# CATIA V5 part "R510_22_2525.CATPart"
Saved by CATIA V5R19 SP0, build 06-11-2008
Material "Steel": density 7860 kg/m3, Young's modulus 2e+11 Pa, Poisson ratio 0.266, thermal expansion 1.17e-05 1/K
Bounding box of the stored display mesh (mm): x -12.497 to 12.497, y -12.358 to 12.439, z 0 to 96
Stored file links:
  G:\Podręcznik\CD\Narzędzia\Arkusz Excel\Modele narzędzi\R510.22-2525.CATPart
  C:\Program Files\Dassault Systemes\B19\intel_a\startup\materials\Catalog.CATMaterial
  F:\OSTATNIE\DesignTable2.xls
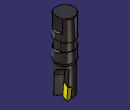
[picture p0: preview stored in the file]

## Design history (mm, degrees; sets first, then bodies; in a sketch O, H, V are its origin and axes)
Parameters
  CuttingType = "CUTTER"
  d = 25 mm {design table}
  D = 25 mm {design table}
  L = 96 mm {design table}
  l = 56 mm {design table}
  alfa = 11 deg {design table}
  gammap = 4 deg {design table}
  S = 4.76 mm {design table}
  epsilon = 85 deg {design table}
  lp = 16 mm {design table}
  x = 0.591 mm {design table}
  gammaf = -10 deg {design table}
  z = 2 {design table}
  teta = 180 deg {design table}
  `lp'` = 15.961 mm {design table}
  `lp''` = 9.4182 mm {design table}
Body1 "BODY" (main body), material "Steel"
  Sketch1 "sketch" on yz-plane, origin (0, 0, 0), H (0, 1, 0), V (0, 0, 1)
    line L1 (0, 2.1258) -> (11.5, 0.7137)
    line L2 (11.5, 0.7137) -> (11.5, 40)
    point P3 (11.5, 40)
    line L3 (11.5, 40) -> (11.5, 40)
    point P4 (12.5, 40)
    line L4 (12.5, 43.2077) -> (12.5, 56.8)
    point P5 (12.5, 56.8)
    line L5 (12.5, 56.8) -> (11.5, 56.8)
    line L6 (11.5, 56.8) -> (11.5, 68)
    line L7 (11.5, 68) -> (12.5, 68)
    point P8 (12.5, 68)
    line L8 (12.5, 68) -> (12.5, 95.2929)
    line L9 (12.5, 95.2929) -> (11.7929, 96)
    line L10 (11.7929, 96) -> (0, 96)
    point P11 (0, 96)
    line L11 (0, 96) -> (0, 2.1258)
    construction line L12 (0, -29.1199) -> (0, 199.3445)
    point P12 (0, -29.1199)
    construction line L13 (0, 0.591) -> (12.5, 0.591)
    point P14 (0, 0.591)
    point P15 (12.5, 0.591)
    construction line L14 (0, 2.1258) -> (12.5, 0.591)
    axis line L15 (12.5, 0.591) -> (12.5, -5.0846)
    line L16 (11.5, 40) -> (12.5, 43.2077)
    point P17 (11.5, 40)
    length L6 = 11.2 {= 0.2*l}
    distance P3 H = 40 {= L-l}
    length L9 = 1
    angle L8 L9 = 45
    distance L6 L8 = 1
    distance L8 L11 = 12.5 {= d/2}
    length L13 = 12.5 {= D/2}
    distance H L13 = 0.591 {= x}
    distance L10 L7 = 28 {= 0.5*l}
    distance P15 L2 = 1
    distance P4 P5 = 16.8 {= 0.3*l}
    length L16 = 3.36 {= 0.2*(0.3*l)}
    angle L1 L2 = 83
    vertical: L2 V, L4 V, L6 V, L8 V, L11 V, L12 V, L15 V
    horizontal: L3 H, L5 H, L7 H, L10 H, L13 H
    coincidence: P8 L4, P11 V, P12 V, L1 L14, P14 L12, L3 P4, L4 P4, P3 P17
  Shaft1: profile Sketch1, axis Z axis, angle 360
  Fillet1: radius 1.25 {= 0.1*D/2}, on edge [face of Shaft1 from Sketch1.L1 | face of Shaft1 from Sketch1.L2]
  Sketch2 on zx-plane, origin (0, 0, 0), H (-1, 0, 0), V (0, 0, 1)
    line L1 (-10.5, 96) -> (-10.5, 79.2)
    line L2 (-10.5, 79.2) -> (-12.5, 77.2)
    line L3 (-12.5, 77.2) -> (-12.5, 70)
    line L4 (-12.5, 70) -> (-10.5, 68)
    point P5 (-10.5, 68)
    line L5 (-10.5, 68) -> (-10.5, 56.8)
    line L6 (-10.5, 56.8) -> (-12.5, 54.8)
    point P7 (-12.5, 54.8)
    line L7 (-12.5, 54.8) -> (-12.5, 54.8)
    line L8 (-12.5, 54.8) -> (-15.5, 54.8)
    line L9 (-15.5, 54.8) -> (-15.5, 96)
    line L10 (-15.5, 96) -> (-10.5, 96)
    reference projected line E1 through (0, 0) direction (0, 1) from axis of face of Shaft1 from Sketch1.L8
    reference projected line E2 (-9.2929, 96) -> (9.2929, 96) from edge [face of Shaft1 from Sketch1.L9 | face of Shaft1 from Sketch1.L10]
    distance L3 E1 = 12.5 {= d/2}
    distance L1 L3 = 2
    angle L2 L3 = 45
    angle L4 L3 = 45
    length L5 = 11.2 {= l*0.2}
    length L1 = 16.8 {= 0.3*l}
    distance P5 L10 = 28 {= 0.5*l}
    distance L9 L1 = 5
    distance L7 L5 = 2
    angle L5 L6 = 45
    vertical: L1 V, L3 V, L5 V, L7 V, L9 V
    horizontal: L8 H, L10 H
    coincidence: L10 E2, L1 L5, P7 L8
  Pocket1: profile Sketch2, direction (0, -1, 0), length 8, mirrored extent
  Plane1: type Angle, Angle 150, Direction Z axis, RefPlane yz-plane
  Plane2: type Offset, Offset 1, RefPlane Plane1, reversed
  Sketch3 "gammap_os_obrotu" on Plane2, origin (0.866, -0.5, 0), H (-0.5, -0.866, 0), V (0, 0, 1)
    line L1 (1.3076, 0) -> (-0.9434, 0)
    reference intersected line E1 through (0, 0) direction (-1, 0) from xy-plane
    horizontal: L1 H
    coincidence: E1 L1
  Plane3 "gammap": type Angle, Angle -4 {= -gammap}, Direction Sketch3, RefPlane Plane2
  Plane4: type Offset, Offset 0.5, RefPlane Plane3, reversed
  Sketch4 on Plane4, origin (1.2859, -0.7424, 0.2345), H (-0.5, -0.866, 0), V (-0.0604, 0.0349, 0.9976)
    line L1 (-12.5, -2.3223) -> (-12.5, 6.2448)
    distance V L1 = 12.5 {= D/2}
  Plane5 "gammaf": type Angle, Angle 10 {= -gammaf}, Direction Sketch4, RefPlane Plane4
  Plane6: type Offset, Offset 0.5, RefPlane Plane5
  Plane7: type Angle, Angle 90, Direction Sketch4, RefPlane Plane5
  Sketch5 on Plane7, origin (3.6272, 11.4982, -0.4755), H (0.9396, -0.3424, 0.0007), V (0.0035, 0.0116, 0.9999)
    point P1 (4.1735, 0.4724)
    line L1 (4.1735, 0.4724) -> (-0.6384, 1.072)
    line L2 (-0.6384, 1.072) -> (-1.6001, 15.1888)
    line L3 (-1.6001, 15.1888) -> (3.086, 16.4354)
    line L4 (3.086, 16.4354) -> (4.1735, 0.4724)
    reference projected line E1 (4.3146, -1.5982) -> (3.7323, 6.9491) from Sketch4
    construction line L5 (3.086, 16.4354) -> (-1.8637, 16.0982)
    axis line L6 (4.1735, 0.4724) -> (0.4479, 0.2186)
    reference intersected line E2 through (-0.0001, 0.4755) direction (-1, 0.0007) from xy-plane
    distance L2 L4 = 4.76 {= S}
    length L4 = 16 {= lp}
    angle L5 L3 = 11 {= alfa}
    angle L6 L1 = 11 {= alfa}
    coincidence: L4 E1, P1 E2
    perpendicularity: L5 L2
    parallelism: L6 L5
  Plane8: type Offset, Offset 12.5 {= D/2}, RefPlane Plane1, reversed
  Sketch6 on Plane8, origin (10.8253, -6.25, 0), H (-0.5, -0.866, 0), V (0, 0, 1)
    line L1 (-2.1396, -3) -> (-2.1396, 25.1125)
    arc A1 centre (-14.1396, 25.1125) radius 12 from (-2.1396, 25.1125) to (-12.5, 37) ccw
    point P4 (-12.5, 37)
    line L2 (-12.5, 37) -> (-12.5, -3)
    point P5 (-12.5, -3)
    line L3 (-12.5, -3) -> (-2.1396, -3)
    axis line L4 (-12.5, -3) -> (-2.1396, -2.0936)
    point P6 (-12.5, -3)
    point P7 (-2.1396, -2.0936)
    reference projected line E1 (-9, 40) -> (9, 40) from edge [face of Shaft1 from Sketch1.L2 | face of Shaft1 from Sketch1.L16]
    distance L2 V = 12.5 {= D/2}
    angle L4 L2 = 85 {= epsilon}
    distance E1 P4 = 3
    radius A1 = 12
    distance H L3 = 3
    length L4 = 10.4 {= 0.65*lp}
    vertical: L1 V, L2 V
    horizontal: L3 H
    tangency: L1 A1
    coincidence: P6 P5, P7 L1
  Pocket2: profile Sketch6, direction (-0.866, 0.5, 0), up to Plane6
  CircPattern1: of Pocket2, instances 2 {= z}, angular step 180 {= teta}, axis from Z axis
  Sketch7 on Plane5, origin (3.4517, -1.0677, 0.6569), H (-0.3414, -0.9399, -0.0041), V (-0.066, 0.0196, 0.9976)
    line L1 (-12.1294, 15.2906) -> (-2.5808, 16.2827)
    point P1 (-12.1294, 15.2906)
    reference projected point E1 (-12.1294, 15.2906) from vertex [element of Sketch5 | element of Sketch5]
    reference projected line E2 (-11.8645, -1.0079) -> (-12.027, 8.9908) from Sketch5.L4
    length L1 = 9.6 {= 0.6*lp}
    angle E2 L1 = 85 {= epsilon}
    coincidence: P1 E1
  Slot1: profile Sketch5, centre curve Sketch7
  CircPattern2: of Slot1, instances 2 {= z}, angular step 180 {= teta}, axis from Z axis
Body2 "INSERTS"
  Sketch8 "CUT" on yz-plane, origin (0, 0, 0), H (0, 1, 0), V (0, 0, 1)
    line L1 (3.1177, 0.8208) -> (12.5, 0)
    point P2 (12.5, 0)
    line L2 (12.5, 0) -> (12.5, 15.961)
    line L3 (12.5, 15.961) -> (3.1177, 16.7819)
    line L4 (3.1177, 16.7819) -> (3.1177, 0.8208)
    angle L3 L4 = 85
    length L2 = 15.961 {= `lp'`}
    length L1 = 9.4182 {= `lp''`}
    distance L2 V = 12.5 {= D/2}
    vertical: L2 V, L4 V
    parallelism: L3 L1
    coincidence: P2 H
  Sketch9 "NOCUT" on yz-plane, origin (0, 0, 0), H (0, 1, 0), V (0, 0, 1)
    axis line L1 (12.5, 0) -> (0, 1.0936)
    point P1 (0, 1.0936)
    point P2 (12.5, 0)
    reference projected line E1 (4.0418, 0.74) -> (10.019, 0.2171) from Sketch8.L1
    reference projected point E2 (12.5, 0) from vertex [element of Sketch8 | element of Sketch8]
    line L2 (0, 1.0936) -> (3.1177, 0.8208)
    point P3 (3.1177, 0.8208)
    line L3 (3.1177, 0.8208) -> (3.1177, 16.7819)
    line L4 (3.1177, 16.7819) -> (11.5, 16.0485)
    line L5 (11.5, 16.0485) -> (11.5, 40)
    line L6 (11.5, 40) -> (12.5, 40)
    line L7 (12.5, 40) -> (12.5, 56.8)
    line L8 (12.5, 56.8) -> (11.5, 56.8)
    line L9 (11.5, 56.8) -> (11.5, 68)
    line L10 (11.5, 68) -> (12.5, 68)
    point P11 (12.5, 68)
    line L11 (12.5, 68) -> (12.5, 95.2929)
    point P12 (12.5, 96)
    line L12 (11.7929, 96) -> (0, 96)
    point P13 (0, 96)
    line L13 (0, 96) -> (0, 1.0936)
    line L14 (12.5, 95.2929) -> (11.7929, 96)
    length L9 = 11.2 {= 0.2*l}
    length L7 = 16.8 {= 0.3*l}
    distance L6 H = 40 {= L-l}
    distance L11 L13 = 12.5 {= d/2}
    distance L9 L11 = 1
    distance P3 P2 = 9.4182 {= `lp''`}
    distance L9 L7 = 1
    distance L5 P2 = 1
    length L3 = 15.961 {= `lp'`}
    angle L10 L9 = 90
    distance P11 P12 = 28 {= 0.5*l}
    angle L11 L14 = 45
    length L14 = 1
    coincidence: P1 V, L1 E1, P2 E2, P13 V, L11 P12, L12 P12
    parallelism: L2 L1, L4 L1
    vertical: L3 V, L5 V, L7 V, L9 V, L11 V, L13 V
    horizontal: L6 H, L8 H, L12 H
  Sketch10 on Plane7, origin (3.6272, 11.4982, -0.4755), H (0.9396, -0.3424, 0.0007), V (0.0035, 0.0116, 0.9999)
    point P1 (4.1735, 0.4724)
    line L1 (4.1735, 0.4724) -> (-0.6384, 1.072)
    line L2 (-0.6384, 1.072) -> (-1.6001, 15.1888)
    line L3 (-1.6001, 15.1888) -> (3.086, 16.4354)
    line L4 (3.086, 16.4354) -> (4.1735, 0.4724)
    reference intersected line E1 through (4.1567, 0.7187) direction (0.068, -0.9977) from Plane5
    reference intersected line E2 through (-0.0001, 0.4755) direction (-1, 0.0007) from xy-plane
    construction line L5 (3.086, 16.4354) -> (-7.8688, 15.6891)
    axis line L6 (4.1735, 0.4724) -> (-2.5007, 0.0177)
    distance L2 L4 = 4.76 {= S}
    length L4 = 16 {= lp}
    angle L3 L5 = 11 {= alfa}
    angle L6 L1 = 11 {= alfa}
    coincidence: L4 E1, E2 P1
    perpendicularity: L5 L2
    parallelism: L6 L5
  Sketch11 on Plane5, origin (3.4517, -1.0677, 0.6569), H (-0.3414, -0.9399, -0.0041), V (-0.066, 0.0196, 0.9976)
    line L1 (-12.1294, 15.2906) -> (-2.5808, 16.2827)
    point P1 (-12.1294, 15.2906)
    reference projected point E1 (-12.1294, 15.2906) from vertex [element of Sketch10 | element of Sketch10]
    reference projected line E2 (-11.8696, -0.696) -> (-12.0321, 9.3027) from Sketch10.L4
    angle L1 E2 = 85 {= epsilon}
    length L1 = 9.6 {= 0.6*lp}
    coincidence: P1 E1
  Rib1: profile Sketch10, centre curve Sketch11
  CircPattern3: of the body so far, instances 2 {= z}, angular step 180 {= teta}, axis from Z axis
  Sketch12 on face of Rib1, origin (0.0936, 0.1801, 1.6188), H (0.7983, -0.5955, -0.09), V (-0.5837, -0.8018, 0.1281)
    point P1 (0.2053, -12.4932)
    line L1 (0.2053, -12.4932) -> (-4.1855, -10.195)
    line L2 (-4.1855, -10.195) -> (-4.4411, -11.1056)
    point P3 (-4.4411, -11.1056)
    line L3 (-4.4411, -11.1056) -> (0.2053, -12.4932)
    reference projected point E1 (0.2053, -12.4932) from vertex [face of Rib1 | face of Rib1 | face of Rib1]
    reference projected line E2 (-3.4802, -11.3926) -> (-0.3761, -12.3196) from edge [face of Rib1 | face of Rib1]
    reference projected point E3 (-4.4411, -11.1056) from vertex [face of Rib1 | face of Rib1 | face of Rib1]
    reference projected line E4 (-3.7698, -8.7135) -> (-2.1488, -2.9367) from edge [face of Rib1 | face of Rib1]
    angle L1 L3 = 11
    coincidence: E1 P1, L3 E2, P3 E3, L2 E4
  Pocket3: profile Sketch12, direction along edge [face of Rib1 | face of Rib1], length 16 {= lp}
  CircPattern4: of Pocket3, instances 2 {= z}, angular step 180 {= teta}, axis from Z axis
Relations
  design table, configuration 5, drives d, D, L, l, alfa, gammap, S, epsilon, lp, x, gammaf, z, teta, `lp'`, `lp''`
